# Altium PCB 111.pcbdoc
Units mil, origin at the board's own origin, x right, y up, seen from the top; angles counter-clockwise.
Board outline 2175 x 2208.3 mil, 2 copper layers (Top Layer, Bottom Layer); 49 components, 50 nets, 197 pads, 92 vias.
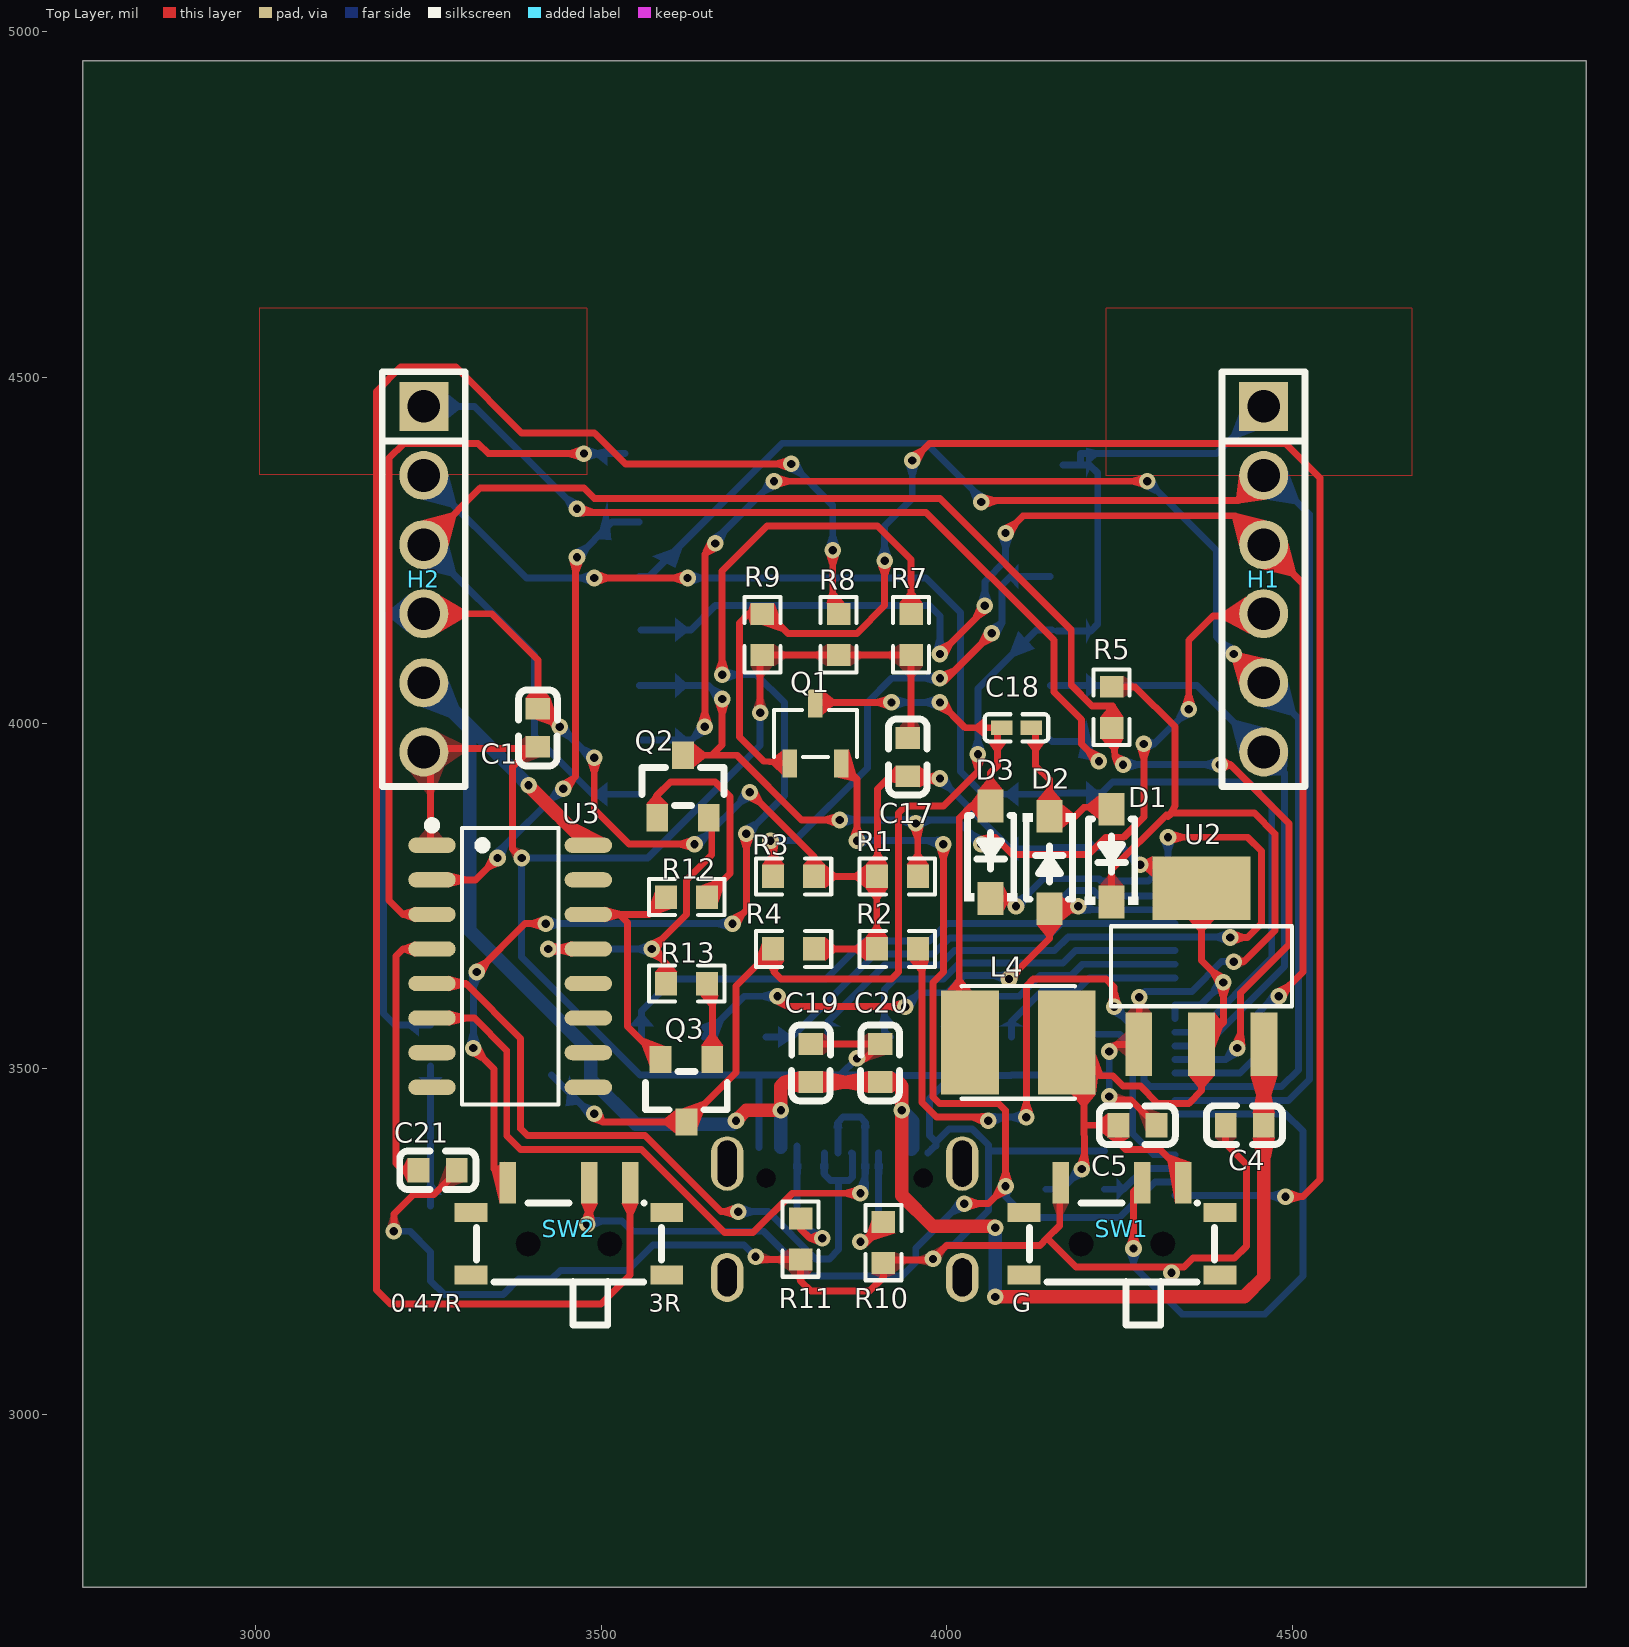
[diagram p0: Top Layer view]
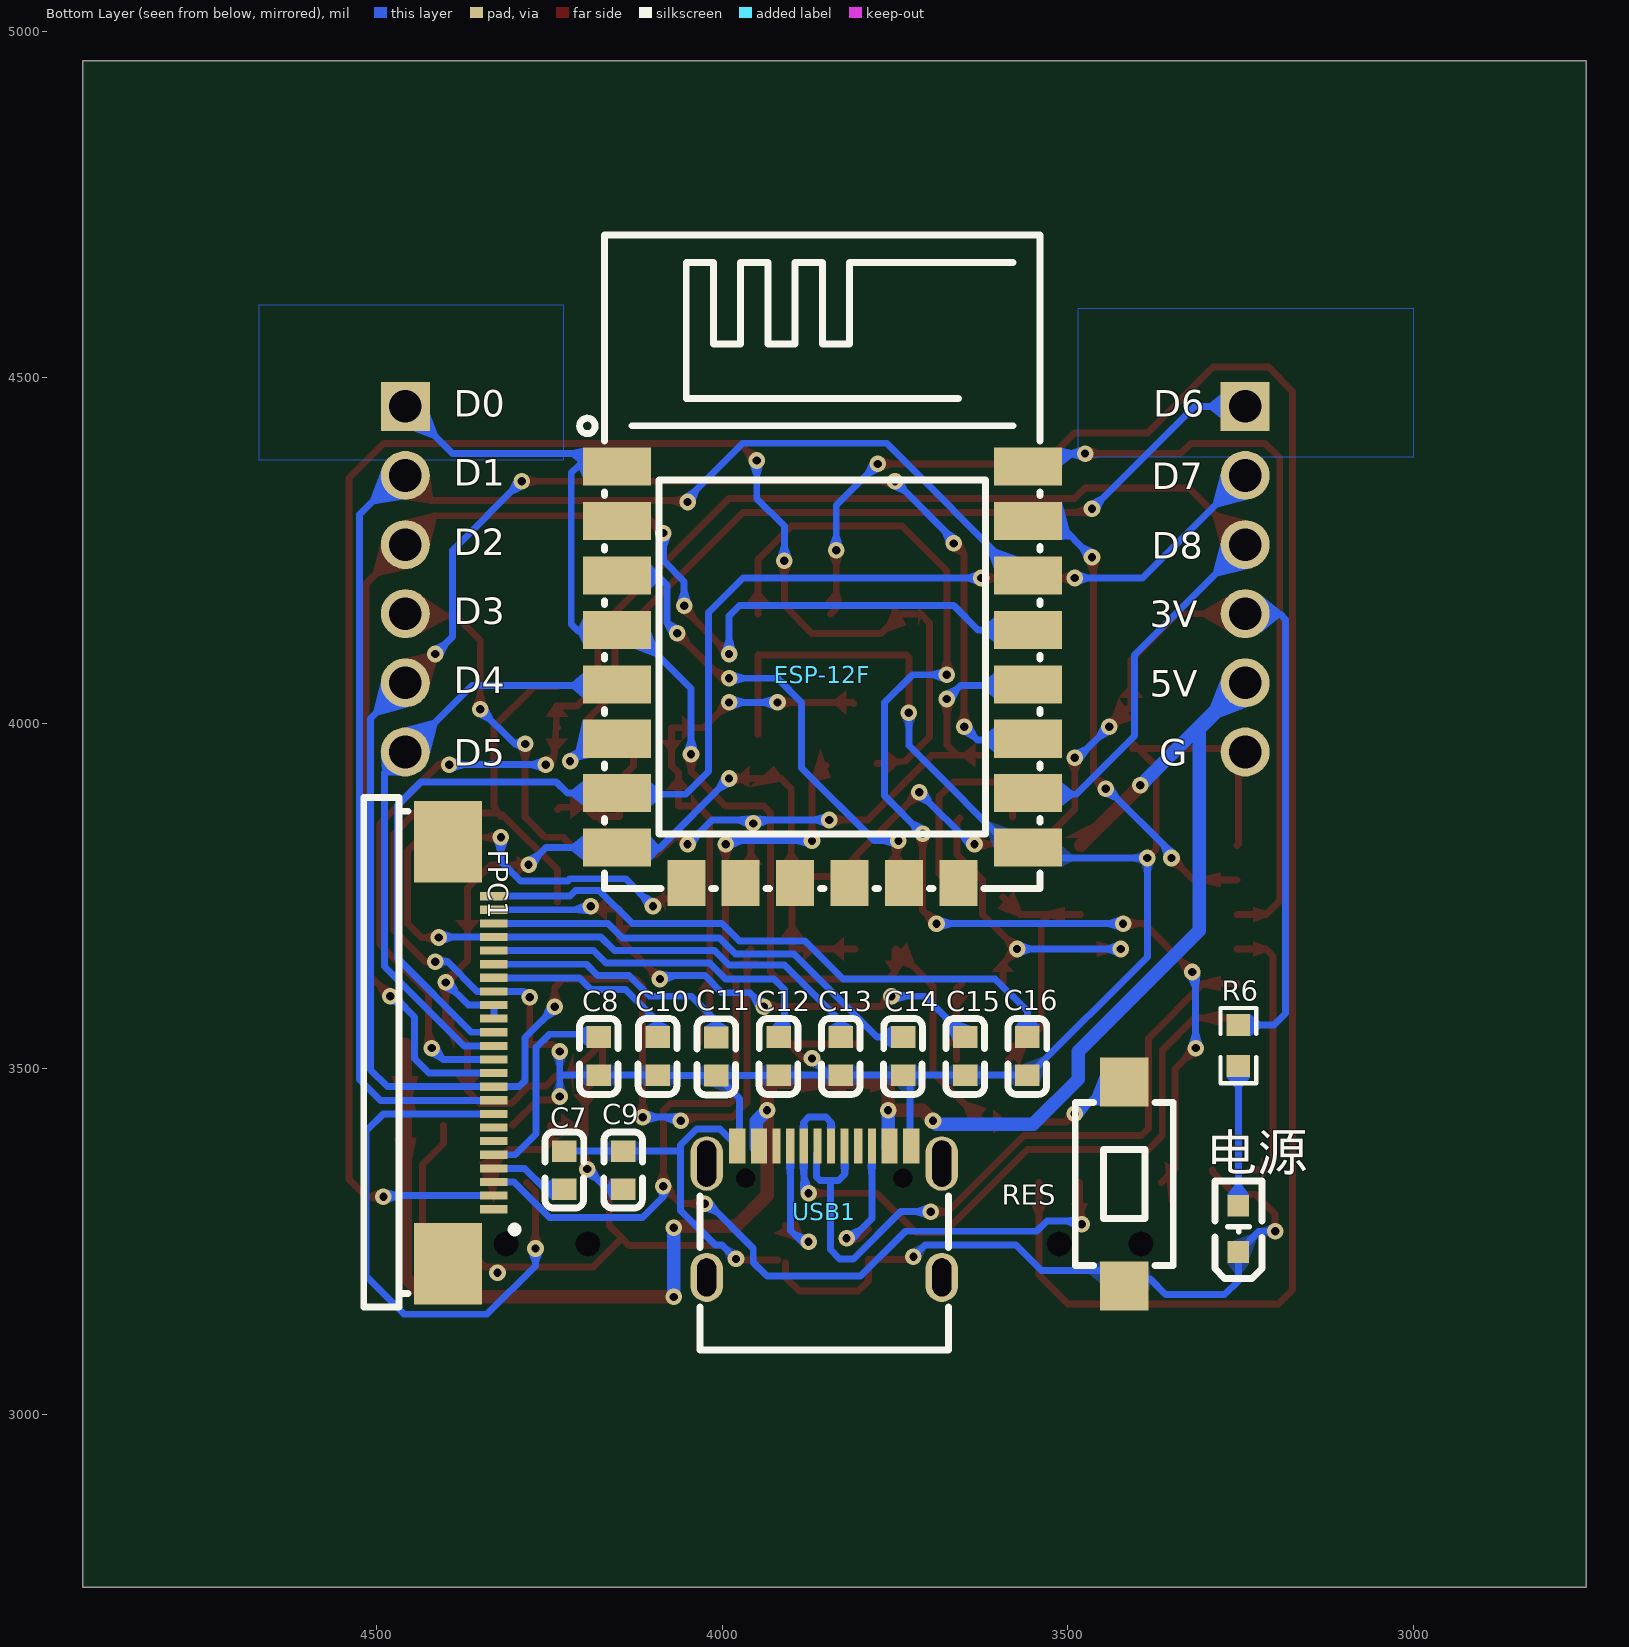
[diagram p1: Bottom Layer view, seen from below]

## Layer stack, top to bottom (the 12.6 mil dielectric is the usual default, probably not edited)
Top Solder: solder mask 0.4, Solder Resist, Dk 3.5
Top Layer: signal copper 1.4
Dielectric 1: dielectric 12.6, FR-4, Dk 4.8
Bottom Layer: signal copper 1.4
Bottom Solder: solder mask 0.4, Solder Resist, Dk 3.5

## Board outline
4925,2750 2750,2750 2750,4958.3 4925,4958.3

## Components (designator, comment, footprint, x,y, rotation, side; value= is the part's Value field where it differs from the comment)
C1 "0.1uF" C0603 3408.56,3993.34 r90 top
C4 "10uF" C0603 4430.9,3418.34 r0 top
C5 "10uF" C0603 4275.78,3418.34 r0 top
C7 "1uF" C0603 4228.34,3353.34 r270 bottom
C8 "1uF" C0603 4178.34,3518.34 r90 bottom
C9 "0.1uF" C0603 4143.34,3353.34 r270 bottom
C10 "1uF" C0603 4093.34,3518.34 r90 bottom
C11 "1uF" C0603 4008.34,3517.73 r90 bottom
C12 "1uF" C0603 3918.34,3518.34 r90 bottom
C13 "1uF" C0603 3828.34,3518.34 r90 bottom
C14 "1uF" C0603 3738.34,3518.34 r90 bottom
C15 "1uF" C0603 3648.34,3518.34 r90 bottom
C16 "1uF" C0603 3558.34,3518.34 r90 bottom
C17 "4.7uF" C0603 3943.34,3950.9 r270 top
C18 "0.1uF" C0402 4100.78,3993.34 r0 top
C19 "0.1uF" C0603 3803.34,3508.34 r270 top
C20 "10uF" C0603 3903.34,3508.34 r270 top
C21 "100nF" C0603 3263.34,3353.34 r180 top
D1 "MBR0530" SOD-123_L2.7-W1.6-LS3.7-RD-1 4238.34,3808.34 r90 top
D2 "MBR0530" SOD-123_L2.7-W1.6-LS3.7-RD-1 4148.34,3798.34 r270 top
D3 "MBR0530" SOD-123_L2.7-W1.6-LS3.7-RD-1 4063.34,3813.34 r90 top
ESP-12F "ESP-12F(ESP8266MOD)" WIFIM-SMD_ESP-12F-ESP8266MOD 3855,4070 r270 bottom
FPC1 "0.5K-BS-24PWB" FPC-SMD_24P-P0.50_HDGC_0.5K-BS-24PWB 4363.34,3523.34 r270 bottom
H1 "Z-211-0611-0021-001" HDR-TH_6P-P2.54-V_Z-211-0611-0021-001 4458.34,4208.34 r270 top
H2 "Z-211-0611-0021-001" HDR-TH_6P-P2.54-V_Z-211-0611-0021-001 3243.34,4208.34 r270 top
L4 "68uH" IND-SMD_L4.0-W4.0_SWPA4018S 4103.34,3538.34 r0 top
Q1 "AO3400" SOT-23-3_L3.0-W1.7-P0.95-LS2.9-BR 3810,3985 r270 top
Q2 "S8050_NPN" SOT-23_L2.9-W1.3-P1.90-LS2.4-BR 3618.34,3908.34 r270 top
Q3 "S8050_NPN" SOT-23_L2.9-W1.3-P1.90-LS2.4-BR 3623.34,3468.34 r90 top
R1 "10kΩ" R0603 3928.34,3778.34 r180 top
R2 "10kΩ" R0603 3928.34,3673.34 r180 top
R3 "10kΩ" R0603 3778.34,3778.34 r0 top
R4 "10kΩ" R0603 3778.34,3673.34 r0 top
R5 "10kΩ" R0603 4238.34,4023 r90 top
R6 "1kΩ" R0603 3253.34,3533.68 r270 bottom
R7 "0.47R" R0603 3948.34,4128 r90 top
R8 "3R" R0603 3843.34,4128 r90 top
R9 "10kΩ" R0603 3733.34,4128 r90 top
R10 "5.1k" R0603 3908.34,3248.68 r90 top
R11 "5.1k" R0603 3788.34,3253.68 r270 top
R12 "10K" R0603 3623.68,3748.34 r0 top
R13 "10K" R0603 3623.68,3623.34 r0 top
RES "TC-3602-4.3-260G" KEY-SMD_L6.0-W3.6-LS8.3-L 3418.34,3333.34 r90 bottom
SW1 "MSK12C02" SW-TH_MSK12C02 4253.34,3268.34 r0 top
SW2 "MSK12C02" SW-TH_MSK12C02 3453.34,3268.34 r0 top
U2 "AMS1117-2.5" SOT-223-3_L6.7-W3.7-P2.30-LS7.0-BR 4368.34,3648.34 r270 top
U3 "CH340C" SOP-16_L10.0-W3.9-P1.27-LS6.0-BL 3368.34,3648.34 r270 top
USB1 "USB_TYPE-C-16P" USB-C-SMD_KH-TYPE-C-16P 3852.32,3293.34 r180 bottom
电源 "19-217/R6C-AL1M2VY/3T" LED0603-R-RD 3253.34,3268.34 r90 bottom

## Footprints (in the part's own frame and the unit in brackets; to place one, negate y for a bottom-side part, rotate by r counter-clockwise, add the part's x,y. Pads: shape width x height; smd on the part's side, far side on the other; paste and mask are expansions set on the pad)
C0402 [mm]
  rect 0.79x0.54 smd: 1(-0.545,0) 2(0.545,0)
  silkscreen extent -1.17,-0.5 1.17,0.5
C0603 [mm]
  rect 0.8x0.9 smd: 1(-0.7,0) 2(0.7,0)
  silkscreen extent -1.41,-0.71 1.39,0.72
FPC-SMD_24P-P0.50_HDGC_0.5K-BS-24PWB [mil]
  rect 11.8x39.4 smd: 1(226.4,33.1) 2(206.7,33.1) 3(187,33.1) 4(167.3,33.1) 5(147.6,33.1) 6(128,33.1) 7(108.3,33.1) 8(88.6,33.1) 9(68.9,33.1) 10(49.2,33.1) 11(29.5,33.1) 12(9.8,33.1) 13(-9.8,33.1) 14(-29.5,33.1) 15(-49.2,33.1) 16(-68.9,33.1) 17(-88.6,33.1) 18(-108.3,33.1) 19(-127.9,33.1) 20(-147.6,33.1) 21(-167.3,33.1) 22(-187,33.1) 23(-206.7,33.1) 24(-226.4,33.1)
  rect 118.1x98.4 smd: 25(-305.1,-33.1) 26(305.1,-33)
  silkscreen extent -369,-155 368,68
HDR-TH_6P-P2.54-V_Z-211-0611-0021-001 [mm]
  rect 1.8x1.8 hole 1.2: 1(-6.35,0)
  round 1.8 hole 1.2: 2(-3.81,0) 3(-1.27,0) 4(1.27,0) 5(3.81,0) 6(6.35,0)
  silkscreen extent -7.62,-1.52 7.62,1.52
IND-SMD_L4.0-W4.0_SWPA4018S [mil]
  rect 83.6x150.4 smd: 1(70,0) 2(-70,0)
  silkscreen extent -82,-82 82,82
KEY-SMD_L6.0-W3.6-LS8.3-L [mm]
  rect 1.8x1.8 smd: 1(-3.75,0) 2(3.75,0)
  silkscreen extent -3,-1.8 3,1.8
LED0603-R-RD [mm]
  rect 0.8x0.8 smd: 1(0.851,0) 2(-0.851,0)
  silkscreen extent -1.82,-0.86 1.77,0.86
R0603 [mil]
  rect 31.75x34.02 smd: 1(-29.66,0) 2(29.66,0)
  silkscreen extent -55,-26 55,26
SOD-123_L2.7-W1.6-LS3.7-RD-1 [mm]
  rect 1.2x0.95 smd: 1(-1.7,0) 2(1.7,0)
  silkscreen extent -1.81,-0.98 1.35,0.98
SOP-16_L10.0-W3.9-P1.27-LS6.0-BL [mm]
  oval 0.56x1.745 smd: 1(-4.445,-2.872) 2(-3.175,-2.872) 3(-1.905,-2.872) 4(-0.635,-2.872) 5(0.635,-2.872) 6(1.905,-2.872) 7(3.175,-2.872) 8(4.445,-2.872) 9(4.445,2.872) 10(3.175,2.872) 11(1.905,2.872) 12(0.635,2.872) 13(-0.635,2.872) 14(-1.905,2.872) 15(-3.175,2.872) 16(-4.445,2.872)
  silkscreen extent -5.33,-3.02 5.08,1.77
SOT-23-3_L3.0-W1.7-P0.95-LS2.9-BR [mil]
  rect 40.85x20.95 smd: 1(43.36,-37.4) 2(43.36,37.4) 3(-43.36,0)
  silkscreen extent -34,-60 34,60
SOT-23_L2.9-W1.3-P1.90-LS2.4-BR [mm]
  rect 1x0.8 smd: 1(1.15,-0.95) 2(1.15,0.95) 3(-1.15,0)
  silkscreen extent -0.7,-1.5 0.7,1.5
SOT-223-3_L6.7-W3.7-P2.30-LS7.0-BR [mm]
  rect 2.34x0.98 smd: 1(2.87,-2.3) 2(2.87,0) 3(2.87,2.3)
  rect 2.34x3.6 smd: 4(-2.87,0)
  silkscreen extent -1.47,-3.33 1.47,3.33
SW-TH_MSK12C02 [mm]
  rect 0.6x1.524 smd: 1(-2.25,1.7) 2(0.75,1.7) 3(2.25,1.7)
  rect 1.2x0.7 smd: 4(-3.6,-1.7) 4(-3.6,0.6) 4(3.6,-1.7) 4(3.6,0.6)
  Multi-Layer board cut-out: -1.05,-0.55 -1.094,-0.355 -1.219,-0.198 -1.4,-0.111 -1.6,-0.111 -1.78,-0.198 -1.905,-0.355 -1.95,-0.55 -1.95,-0.55 -1.905,-0.745 -1.78,-0.902 -1.6,-0.989 -1.4,-0.989 -1.219,-0.902 -1.094,-0.745 -1.05,-0.55
  Multi-Layer board cut-out: 1.95,-0.55 1.906,-0.355 1.781,-0.198 1.6,-0.111 1.4,-0.111 1.22,-0.198 1.095,-0.355 1.05,-0.55 1.05,-0.55 1.095,-0.745 1.22,-0.902 1.4,-0.989 1.6,-0.989 1.781,-0.902 1.906,-0.745 1.95,-0.55
  silkscreen extent -3.4,-3.53 3.4,0.95
USB-C-SMD_KH-TYPE-C-16P [mm]
  oval 1.2x2 hole 0.7 slot 1.7 at 90 deg: 1(-4.32,1.765) 2(4.32,1.765)
  oval 1.2x1.8 hole 0.7 slot 1.4 at 90 deg: 3(-4.32,-2.415) 4(4.32,-2.415)
  rect 0.3x1.3 smd: A1(-3.35,2.415) A4(-2.55,2.415) A5(-1.25,2.415) A6(-0.25,2.415) A7(0.25,2.415) A8(1.25,2.415) A9(2.55,2.415) A12(3.35,2.415) B1(3.05,2.415) B4(2.25,2.415) B5(1.75,2.415) B6(0.75,2.415) B7(-0.75,2.415) B8(-1.75,2.415) B9(-2.25,2.415) B12(-3.05,2.415)
  Multi-Layer board cut-out: -3.24,1.235 -3.205,1.387 -3.108,1.509 -2.968,1.576 -2.812,1.576 -2.672,1.509 -2.575,1.387 -2.54,1.235 -2.54,1.235 -2.575,1.083 -2.672,0.961 -2.812,0.894 -2.968,0.894 -3.108,0.961 -3.205,1.083 -3.24,1.235
  Multi-Layer board cut-out: 2.54,1.235 2.575,1.387 2.672,1.509 2.812,1.576 2.968,1.576 3.108,1.509 3.205,1.387 3.24,1.235 3.24,1.235 3.205,1.083 3.108,0.961 2.968,0.894 2.812,0.894 2.672,0.961 2.575,1.083 2.54,1.235
  silkscreen extent -4.57,-5.08 4.57,0.57
WIFIM-SMD_ESP-12F-ESP8266MOD [mil]
  rect 55.1x98.4 smd: 1(-301.2,-297.3) 2(-222.5,-297.3) 3(-143.7,-297.3) 4(-65,-297.3) 5(13.8,-297.3) 6(92.5,-297.3) 7(171.2,-297.3) 8(250,-297.3) 9(250,297.2) 10(171.2,297.3) 11(92.5,297.3) 12(13.8,297.3) 13(-65,297.2) 14(-143.7,297.3) 15(-222.5,297.3) 16(-301.2,297.3)
  rect 66.9x55.1 smd: 17(301.2,-196.8) 18(301.1,-118.2) 19(301.2,-39.5) 20(301.2,39.3) 21(301.2,118) 22(301.2,196.7)
  silkscreen extent -636,-351 309,315

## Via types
v1: diameter 24.02, hole 12.01, Top Layer to Bottom Layer, 92 vias

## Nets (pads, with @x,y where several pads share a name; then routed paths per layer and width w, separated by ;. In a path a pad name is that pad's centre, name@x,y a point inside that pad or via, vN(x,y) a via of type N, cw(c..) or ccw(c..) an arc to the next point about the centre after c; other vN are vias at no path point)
1: FPC1.3 Q1.2 SW2.2 | length 1900.6
  Top Layer w10: v1(3480,3275) 3482.87,3277.87 SW2.2 ; Q1.2@3850,3939.04 3870,3919.04 v1(3870,3830) ; v1(3995,3825) 3995,3640 3980,3625 3980,3459.13 3989.13,3450 4075,3450 4085,3440 v1(4085,3330) 4060,3305 v1(4025,3305)
  Bottom Layer w10: v1(3480,3275) 3485,3280 3530,3280 3545,3265 3735,3265 3800,3200 3935,3200 3955,3220 3955,3240 4020,3305 v1(4025,3305) ; v1(3870,3830) 3990,3830 v1(3995,3825) ; v1(4085,3330) 4085,3315 4115,3285 4250,3285 4301.34,3336.34 FPC1.3
2: R8.2 SW2.3 | length 2744.1
  Top Layer w10: SW2.3 3541.92,3201.92 3500,3160 3195,3160 3175,3180 3175,4480 3210,4515 3290,4515 3385,4420 3490,4420 3535,4375 v1(3775,4375) ; v1(3835,4250) 3835,4166.01 R8.2
  Bottom Layer w10: v1(3775,4375) 3835,4315 v1(3835,4250)
3: R7.2 SW2.1 | length 1733.3
  Top Layer w10: v1(3315,3530) 3345,3500 3345,3355.04 SW2.1 ; v1(3320,3640) 3390,3710 v1(3420,3710) ; v1(3675,4070) 3675,4220 3740,4285 3900,4285 3948.34,4236.66 R7.2 ; v1(3690,3710) 3710,3730 v1(3710,3840)
  Bottom Layer w10: v1(3315,3530) 3315,3635 v1(3320,3640) ; v1(3420,3710) v1(3690,3710) ; v1(3675,4070) 3725,4070 3765,4030 3765,3895 v1(3710,3840)
8: FPC1.8 SW1.2 | length 827.4
  Top Layer w10: v1(4270,3240) 4270,3322.4 SW1.2
  Bottom Layer w10: v1(4270,3240) 4270,3215 4340,3145 4460,3145 4515,3200 4515,3410 4490.26,3434.74 FPC1.8
$1N49910: R6.2 电源.1 | length 202.2
  Bottom Layer w10: 电源.1 R6.2
$1N54347: C7.2 | length 114.4
  Bottom Layer w10: C7.2 4255.78,3325.78 4286.04,3356.04 4330.24,3356.04
$1N54363: C8.2 | length 299
  Bottom Layer w10: C8.2 4182.44,3550 4250,3550 4269,3531 4269,3406 4299.26,3375.74 4330.24,3375.74
$1N55661: C10.2 | length 285.6
  Bottom Layer w10: C10.2 4093.34,3568.34 4140,3615 4190,3615 4206.64,3631.64 4330.24,3631.64
$1N55690: C11.2 | length 379.3
  Bottom Layer w10: C11.2 4008.34,3568.34 4045,3605 4105,3605 4135,3635 4180,3635 4196.24,3651.24 4330.24,3651.24
$1N55719: C12.2 | length 516
  Bottom Layer w10: C12.2 3910,3554.25 3910,3615 3925,3630 3995,3630 4018.01,3653.01 4168.01,3653.01 4185.94,3670.94 4330.24,3670.94
$1N55777: C14.2 | length 660
  Bottom Layer w10: C14.2 3775.9,3545.9 3896,3666 3981,3666 4004,3689 4144,3689 4165,3710 4329.9,3710 4330.24,3710.34
$1N55910: C16.2 | length 885.1
  Bottom Layer w10: C16.2 3558.34,3583.34 3605,3630 3825,3630 3880,3685 3975,3685 4000,3710 4130,3710 4178.01,3758.01 4211.99,3758.01 4220,3750 4329.99,3750 4330.24,3749.74
$1N60025: C18.1 D3.2 L4.2 Q1.3 | length 779.8
  Top Layer w10: Q1.3 3811.64,4030 v1(3920,4030) ; v1(3990,4030) 4026.66,3993.34 4073.22,3993.34 4073.22,3938.22 4063.34,3928.34 D3.2 4035.27,3880.27 4018.01,3863.01 4018.01,3583.68 4033.34,3568.34 L4.2
  Bottom Layer w10: v1(3920,4030) v1(3990,4030)
$1N60403: C18.2 D1.2 D2.1 | length 233
  Top Layer w10: C18.2@4128.34,3993.34 4128.34,3938.34 4148.34,3918.34 D2.1 4185.27,3865.27 4198.34,3878.34 4235.27,3878.34 D1.2
$1N77678: R10.2 USB1.A5 | length 188.3
  Top Layer w10: v1(3875,3250) 3885,3250 R10.2@3908.34,3273.34
  Bottom Layer w10: v1(3875,3250) 3885,3250 3901.35,3266.35 3901.35,3378.24 USB1.A5@3901.53,3378.42
$1N79361: R11.1 USB1.B5 | length 190.7
  Top Layer w10: R11.1@3788.34,3268.34 3801.69,3255 v1(3820,3255)
  Bottom Layer w10: USB1.B5 3783.34,3388.35 3783.34,3283.34 3811.69,3255 v1(3820,3255)
$1N89698: Q2.1 R12.2 | length 313.3
  Top Layer w10: Q2.1@3580,3864.01 3580,3895 3600,3915 3665,3915 3686.22,3893.78 3686.22,3782.35 3653.34,3749.48 R12.2
$1N89804: Q3.1 R13.2 | length 112.8
  Top Layer w10: R13.2 3660.75,3615.94 Q3.1
$1N90351: C21.2 U3.4 | length 392.6
  Top Layer w10: C21.2 3213.34,3353.34 3203.34,3363.34 3203.34,3663.34 3213.34,3673.34 U3.4
$1N94225: Q3.2 R12.1 U3.14 | length 357.2
  Top Layer w10: U3.14 3526.66,3723.34 ; Q3.2 3538.34,3561.22 3538.34,3711.66 3526.66,3723.34 ; R12.1 3569.02,3723.34 3526.66,3723.34
$1N94557: Q2.2 R13.1 U3.13 | length 494
  Top Layer w10: v1(3423.34,3673.34) U3.13 ; R13.1 3594.02,3652.66 v1(3573.34,3673.34) 3623.34,3723.34 3623.34,3773.34 3660,3810 3660,3858.81 Q2.2
  Bottom Layer w10: v1(3423.34,3673.34) v1(3573.34,3673.34)
$3N116693: FPC1.4
$3N116770: FPC1.5
$3N117995: FPC1.18
$3N118097: FPC1.19
$3N118201: FPC1.20
$3N118416: FPC1.22
$3N118639: FPC1.24
+3V: C1.2 C5.1 C9.2 C17.2 ESP-12F.8 FPC1.15 FPC1.16 H2.4 L4.1 R1.2 R2.2 R3.2 R4.2 R6.1 SW1.3 U2.2 U2.4 | length 3684.4
  Top Layer w10: H2.4 3341.66,4158.34 3408.56,4091.44 C1.2 3414.1,4020.9 v1(3440,3995) ; v1(3490,3950) 3490,3875 3540,3825 v1(3635,3825) ; v1(3715,3900) 3808,3807 R3.2 R1.2 ; R4.2 R2.2 R1.2 ; v1(3990,3920) 3915,3920 3900,3905 3900,3779.66 R1.2 ; v1(4195,3355) 4200,3360 4198.28,3418.34 ; L4.1@4200,3480 4195,3475 L4.1@4192.38,3475 ; 4253.7,3476.3 4240,3490 4221.69,3490 L4.1 4173.34,3496.66 L4.1@4192.38,3475 ; 4255,3475 4280,3475 4305,3450 4350,3450 4368.34,3468.34 U2.2 4400,3567.01 v1(4400,3625) 4368.34,3656.66 U2.4 4334.68,3795 v1(4280,3795) ; SW1.3 4341.92,3349.76 4308.34,3383.34 4258.34,3383.34 4248.22,3393.46 C5.1 4198.28,3418.34 ; L4.1@4192.38,3475 4191.57,3475 L4.1@4198.28,3468.28 ; L4.1@4192.38,3475 L4.1@4198.28,3468.28 ; 4198.28,3418.34 L4.1@4198.28,3468.28
  Bottom Layer w10: H2.4 3193.34,4158.34 3185,4150 3185,3580 3201.66,3563.34 R6.1 ; v1(3440,3995) 3485,3950 v1(3490,3950) ; v1(3635,3825) 3640,3825 v1(3715,3900) ; v1(3990,3920) 4091.66,3818.34 ESP-12F.8@4149.62,3818.34 ; C9.2 4165.78,3325.78 v1(4195,3355) ; ESP-12F.8 4255,3820 v1(4280,3795) ; FPC1.15 FPC1.16 4367.24,3592.24 v1(4400,3625)
+5V: C4.2 C19.2 C20.2 H2.5 U2.3 U3.16 USB1.A4 USB1.A9 USB1.B4 USB1.B9 | length 2794.4
  Top Layer w19.68: v1(3395,3910) 3395,3909.78 U3.16 ; v1(3695,3425) 3710,3440 v1(3760,3440) 3760,3475 3765.78,3480.78 C19.2 C20.2 3929.22,3480.78 3935,3475 v1(3935,3440) 3935,3316.69 3979.54,3272.15 4067.85,3272.15 v1(4070,3270) ; v1(4070,3170) 4430,3170 4458.46,3198.46 C4.2 4458.46,3534.92 U2.3
  Bottom Layer w19.68: 3370,3935 3246.66,4058.34 H2.5 3310,3991.69 3310,3700 3485,3525 3485,3485 3550,3420 3690,3420 v1(3695,3425) ; 3375,3930 v1(3395,3910) ; USB1.B4@3760,3386.49 v1(3760,3440) ; v1(3935,3440) 3950.65,3424.35 3950.65,3385.73 USB1.A4@3948.34,3383.42 ; v1(4070,3170) v1(4070,3270)
ADC: ESP-12F.2
D+: U3.5 USB1.A6 USB1.B6 | length 1048.3
  Top Layer w10: U3.5 3304.12,3623.34 3383.34,3544.12 3383.34,3413.34 3393.34,3403.34 3563.34,3403.34 3673.34,3293.34 v1(3698.34,3293.34)
  Bottom Layer w10: v1(3698.34,3293.34) 3741.66,3293.34 3810,3225 3830,3225 3843.34,3238.34 3843.34,3338.34 ; USB1.B6@3822.79,3378.42 3822.79,3347.21 3831.66,3338.34 3843.34,3338.34 ; USB1.A6@3862.16,3378.42 3863.34,3377.24 3863.34,3343.34 3858.34,3338.34 3843.34,3338.34
D-: U3.6 USB1.A7 USB1.B7 | length 1039.2
  Top Layer w10: U3.6 3316.66,3573.34 3363.34,3526.66 3363.34,3403.34 3383.34,3383.34 3558.34,3383.34 3678.34,3263.34 3719.9,3263.34 3776.56,3320 v1(3875,3320)
  Bottom Layer w10: USB1.A7@3842.48,3378.42 3842.48,3422.48 3850,3430 3875,3430 3881.85,3423.15 USB1.B7 3881.85,3326.85 v1(3875,3320)
EN: ESP-12F.3 R3.1 | length 703.9
  Top Layer w10: v1(3745,3830) 3748.68,3826.32 R3.1 ; v1(3990,4065) 4000,4065 v1(4065,4130)
  Bottom Layer w10: v1(3745,3830) 3780,3830 3885,3935 3885,4030 3920,4065 v1(3990,4065) ; v1(4065,4130) 4080,4145 4080,4200 4092.04,4212.04 ESP-12F.3@4149.62,4212.04
GDR: FPC1.2 Q1.1 R9.2 | length 2590.5
  Top Layer w10: Q1.1 3775.96,3941.64 3735,3945 3700,3980 3700,4145 3712.66,4157.66 R9.2 3742.34,4157.66 3770,4130 3870,4130 3910,4170 v1(3910,4235) ; v1(3950,4380) 3974.78,4404.78 4490.22,4404.78 4540,4355 4540,3340 4515,3315 v1(4490,3315)
  Bottom Layer w10: v1(3910,4235) 3910,4285 3950,4325 v1(3950,4380) ; FPC1.2 4488.36,3316.64 v1(4490,3315) v1@4495,3315
GND: C1.1 C4.1 C5.2 C7.1 C8.1 C9.1 C10.1 C11.1 C12.1 C13.1 C14.1 C15.1 C16.1 C17.1 C19.1 C20.1 C21.1 D1.1 ESP-12F.9 FPC1.17 H2.6 R5.2 R7.1 R8.1 R9.1 R10.1 R11.2 RES.1 SW1.1 U2.1 U3.1 USB1.A1 USB1.A12 USB1.B1 USB1.B12 电源.2 | length 6385.4
  Top Layer w10: v1(3200,3265) 3200,3290 3228.34,3318.34 3258.34,3318.34 3290.9,3350.9 C21.1 ; H2.6 H2.6@3248.34,3963.34 ; U3.1 3253.34,3825.25 3253.34,3958.34 H2.6@3248.34,3963.34 ; v1(3385,3805) 3371.99,3818.01 3371.99,3936.99 C1.1@3398.34,3963.34 ; C1.1@3406.12,3963.34 C1.1@3398.34,3963.34 ; C1.1@3408.34,3973.34 C1.1@3398.34,3963.34 ; v1(3723.34,3228.34) 3727.66,3224.02 R11.2 3788.34,3193.34 3803.34,3178.34 3888.34,3178.34 3908.34,3198.34 R10.1 ; v1(3730,4015) 3730,4095 R9.1 R8.1 R7.1 C17.1@3948.34,3983.46 ; C19.1 C20.1 3882.44,3515 v1(3870,3515) ; R10.1@3919.02,3223.34 3978.34,3223.34 v1(3980,3225) 3999.7,3244.7 4134.7,3244.7 4145,3255 ; SW1.1 4163.34,3333.85 4163.34,3273.34 4145,3255 ; v1(4235,3460) 4240,3455 4266.69,3455 C5.2 ; v1(4235,3525) 4245.35,3535.35 U2.1 4278.34,3535.9 v1(4278.34,3603.34) ; D1.1 4238.34,3788.34 4317.5,3867.5 4320,3865 4322.5,3867.5 ; R5.2 4272.34,4052.66 4330,3995 4330,3880 4322.5,3867.5 ; C4.1 4403.34,3391.66 4433.34,3361.66 4433.34,3243.34 4416.19,3226.19 4356.19,3226.19 4343.34,3213.34 4186.66,3213.34 4145,3255 ; v1(4415,3655) 4430,3655 4475,3700 4475,3840 4445,3870 4325,3870 4322.5,3867.5 ; H2.6@3248.34,3963.34 C1.1@3398.34,3963.34
  Bottom Layer w10: v1(3200,3265) 3223.19,3265 电源.2 3253.34,3193.34 3273.34,3173.34 3358.34,3173.34 3380.7,3195.7 3428.34,3195.7 3440.98,3208.34 3538.34,3208.34 3575,3245 3706.69,3245 v1(3723.34,3228.34) ; USB1.B1@3728.34,3386.34 C14.1@3728.34,3490.78 ; v1(3730,4015) 3730,3967.63 3567.37,3805 v1(3385,3805) 3385,3661.69 3555.9,3490.78 C16.1 C15.1 C14.1@3728.34,3490.78 ; v1(3870,3515) C13.1@3845.78,3490.78 ; USB1.B12@3972.4,3378.42 USB1.B12@3975.37,3381.4 ; USB1.B12@3977.75,3383.34 USB1.A1@3984.21,3388.64 ; v1(3980,3225) 4000,3245 4010,3245 4060,3295 4060,3380.9 4060.9,3380.9 ; USB1.A1 USB1.A1@3984.21,3388.64 ; C7.1 C9.1 4060.9,3380.9 ; v1(4235,3460) 4235,3490 ; v1(4235,3525) 4235,3490 ; v1(4278.34,3603.34) 4286.94,3611.94 FPC1.17 4354.41,3611.94 4397.46,3655 v1(4415,3655) ; C14.1@3728.34,3490.78 C14.1 C13.1 C13.1@3845.78,3490.78 ; C13.1@3845.78,3490.78 C12.1 3918.95,3490.17 C11.1 ; USB1.A1@3984.21,3388.64 USB1.A1@3984.21,3394.21 ; USB1.A1@3984.21,3394.21 4003.2,3413.2 4036.8,3413.2 4060,3390 4060,3381.81 4060.9,3380.9 ; USB1.A1@3984.21,3394.21 3975,3403.42 3975,3456.83 C11.1 ; C11.1 4092.73,3490.17 C10.1 C8.1 4234.22,3490.78 4235,3490
  other v1: 4325,3205
GPIO0: ESP-12F.12 H1.4 Q2.3 R1.1 | length 1470.4
  Top Layer w10: Q2.3 3660,3953.62 ; v1(3675,4035) 3675,3968.62 3660,3953.62 ; v1(3845,3860) 3790,3860 3696.38,3953.62 3660,3953.62 ; v1(3955,3855) 3958,3852 R1.1 ; v1(4050,3825) 4060,3835 4070,3835 4095,3810 4205,3810 4230,3835 4255.95,3835 4285,3864.05 v1(4285,3970) ; v1(4350,4020) 4350,4120 4385,4155 4455,4155 H1.4
  Bottom Layer w10: ESP-12F.12@3555.02,4054.54 3655.46,4054.54 v1(3675,4035) ; v1(3845,3860) 3950,3860 v1(3955,3855) 3960,3860 4015,3860 v1(4050,3825) ; v1(4285,3970) 4300,3970 v1(4350,4020)
GPIO2: ESP-12F.11 FPC1.10 H1.5 R2.1 | length 3093.3
  Top Layer w10: v1(3650,3995) 3650,4245 v1(3665,4260) ; v1(3750,4350) v1(4290,4350) ; R2.1 3964,3667.35 3964,3451 3985,3430 4055,3430 v1(4060,3425) ; v1(4115,3430) 4115,3620 4125,3630 4230,3630 4242.19,3617.81 v1(4242.19,3590) ; v1(4415,4100) 4456.66,4058.34 H1.5
  Bottom Layer w10: ESP-12F.11@3555.02,3975.84 3630.84,3975.84 v1(3650,3995) ; v1(3665,4260) 3665,4265 v1(3750,4350) ; v1(4060,3425) 4065,3430 v1(4115,3430) ; v1@4235,3590 4240,3590 4285,3545 4285,3482.72 4293.57,3474.14 FPC1.10 4484.14,3474.14 4508.5,3498.5 4508.5,4006.5 4458.34,4056.66 H1.5 ; v1(4290,4350) 4390,4250 4390,4125 v1(4415,4100)
GPIO4: ESP-12F.13 FPC1.11 H1.3 | length 2033.4
  Top Layer w10: v1(3990,4100) 4055,4165 v1(4055,4170) ; v1(4085,4275) 4110,4300 4416.69,4300 H1.3 4515,4201.69 4515,3640 v1(4480,3605)
  Bottom Layer w10: ESP-12F.13 3630,4135 3665,4170 3975,4170 3990,4155 v1(3990,4100) ; v1(4055,4170) 4055,4205 4085,4235 v1(4085,4275) ; FPC1.11 4423.84,3493.84 4445,3515 4445,3575 v1@4470,3600
GPIO5: ESP-12F.14 FPC1.9 H1.2 | length 2151.1
  Top Layer w10: v1(4050,4320) 4051.99,4321.99 4421.99,4321.99 H1.2
  Bottom Layer w10: ESP-12F.14@3555.02,4212.04 3569.55,4212.04 3762.51,4405 3970,4405 4050,4325 v1(4050,4320) ; FPC1.9 4494.44,3454.44 4524.5,3484.5 4524.5,4302.19 4468.34,4358.34 H1.2
GPIO12: ESP-12F.6 H2.1 | length 1336.9
  Top Layer w10: v1(3465,4310) 3470,4305 3970,4305 4155,4120 4155,4045 4195,4005 4195,3970 v1(4220,3945)
  Bottom Layer w10: H2.1 3316.66,4458.34 v1(3465,4310) ; ESP-12F.6@4149.62,3975.84 4152.12,3973.34 4191.66,3973.34 v1(4220,3945)
GPIO13: ESP-12F.7 FPC1.14 H2.2 | length 1967.4
  Top Layer w10: v1(3490,4210) v1(3625,4210)
  Bottom Layer w10: H2.2 3391.69,4210 v1(3490,4210) ; v1(3625,4210) 3970,4210 4020,4160 4020,3930 4052.86,3897.14 ESP-12F.7@4141.35,3897.14 ; ESP-12F.7 4223.8,3898.8 4240,3915 4436.02,3915 4470,3881.02 4470,3660 4362.84,3552.84 FPC1.14
GPIO14: ESP-12F.5 FPC1.13 H1.6 | length 876.8
  Bottom Layer w10: ESP-12F.5@4149.62,4054.54 4362.14,4054.54 H1.6 4488.34,3928.34 4488.34,3648.34 4373.14,3533.14 FPC1.13
GPIO15: ESP-12F.10 FPC1.12 H2.3 R5.1 | length 2534.5
  Top Layer w10: H2.3@3260,4275 3325,4340 3475,4340 3490,4325 3990,4325 4180,4135 4180,4055 4210,4025 4240,4025 R5.1@4240,3995.34 ; R5.1 4240,3995 R5.1@4240,3995.34 ; v1(4255,3940) 4243.01,3951.99 R5.1@4240,3995.34 ; v1(4395,3940) 4410,3940 4495,3855 4495,3680 4425,3610 4425,3535 v1(4420,3530)
  Bottom Layer w10: H2.3 3403.34,4098.34 3403.34,3981.66 3487.86,3897.14 ESP-12F.10@3555.02,3897.14 ; v1(4255,3940) v1(4395,3940) ; FPC1.12 4403.54,3513.54 v1(4420,3530)
GPIO16: ESP-12F.1 ESP-12F.4 H1.1 Q3.3 R4.1 RES.2 | length 2026
  Top Layer w10: v1(3490,3435) 3501.66,3423.34 3623.34,3423.34 Q3.3 3695,3494.73 3695,3619.66 R4.1 3750,3672.03 3750,3640 3760,3630 3920,3630 3930,3640 3930,3870 3940,3880 3995,3880 4045,3930 v1(4045,3955)
  Bottom Layer w10: RES.2@3428.34,3490.98 3484.33,3435 v1(3490,3435) ; v1(4045,3955) 4045,4050 4130,4135 ESP-12F.4 ; ESP-12F.4@4159.62,4133.34 4208.34,4133.34 4218.34,4143.34 4218.34,4361.66 4206.66,4373.34 ESP-12F.1@4193.34,4373.34 ; ESP-12F.1@4168.34,4373.34 ESP-12F.1@4193.34,4373.34 ; H1.1 4390,4390 4193.34,4390 ESP-12F.1@4193.34,4373.34
PREVGH: C13.2 D3.1 FPC1.21 | length 1277.4
  Top Layer w10: D3.1 4088.59,3746.41 v1(4100,3735) ; v1(4320,3835) 4435,3835 4455,3815 4455,3710 4435,3690 v1(4410,3690)
  Bottom Layer w10: C13.2 3828.34,3568.34 3910,3650 3990,3650 4011,3671 4156,3671 4175.64,3690.64 FPC1.21 4409.36,3690.64 v1(4410,3690) ; v1(4100,3735) 4140,3775 4220,3775 4223.01,3771.99 4291.99,3771.99 4320,3800 v1@4320,3830
PREVGL: C15.2 D2.2 FPC1.23 | length 804.1
  Top Layer w10: v1(3755,3605) 3770,3590 v1(3940,3590) ; v1(4090,3630) 4148.34,3688.34 D2.2 4186.41,3731.41 v1(4190,3735)
  Bottom Layer w10: C15.2 3707.44,3605 v1(3755,3605) ; v1(3940,3590) 3960,3610 4000,3610 4025,3635 4085,3635 v1(4090,3630) ; v1(4190,3735) 4194.96,3730.04 FPC1.23
RX: ESP-12F.15 U3.2 | length 703.1
  Top Layer w10: U3.2 3318.34,3773.34 v1(3350,3805) ; v1(3445,3905) 3463.01,3923.01 3463.01,4238.01 v1(3465,4240)
  Bottom Layer w10: v1(3350,3805) 3350,3812.54 3442.46,3905 v1(3445,3905) ; v1(3465,4240) 3515.84,4290.84 ESP-12F.15@3555.02,4290.84
TX: ESP-12F.16 U3.3 | length 1066.4
  Top Layer w10: U3.3 3213.34,3723.34 3193.34,3743.34 3193.34,4383.34 3214.78,4404.78 3321.91,4404.78 3336.69,4390 v1(3475,4390)
  Bottom Layer w10: v1(3475,4390) ESP-12F.16@3534.56,4390
"": 
pads on no net: ESP-12F.17 ESP-12F.18 ESP-12F.19 ESP-12F.20 ESP-12F.21 ESP-12F.22 FPC1.1 FPC1.6 FPC1.7 FPC1.25 FPC1.26 SW1.4 SW2.4 U3.7 U3.8 U3.9 U3.10 U3.11 U3.12 U3.15 USB1.1 USB1.2 USB1.3 USB1.4 USB1.A8 USB1.B8

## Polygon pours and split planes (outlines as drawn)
GND on Bottom Layer (solid): 3000,3000 4675,3000 4675,4405 3000,4405
GND on Top Layer (solid, pour order 1): 3005,3000 4675,3000 4675,4405 3005,4405
GND on Top Layer (solid, pour order 2): 3005,4360 3480,4360 3480,4600 3005,4600
GND on Top Layer (solid, pour order 3): 4230,4358.34 4672.99,4358.34 4672.99,4600 4230,4600
GND on Bottom Layer (solid, pour order 4): 4230,4380 4670,4380 4670,4605 4230,4605
GND on Bottom Layer (solid, pour order 5): 3000,4385 3485,4385 3485,4600 3000,4600

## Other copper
Top Layer:
  region net +5V: 4448.62,3465.59 4442.72,3436.06 4474.21,3436.06 4468.31,3465.59
  region net +5V: 4448.62,3371.1 4468.31,3371.1 4474.21,3400.63 4442.72,3400.63
  region net +3V: 4373.34,3474.29 4385.84,3489.29 4350.84,3489.29 4363.34,3474.29
  region net +3V: 4398.24,3558.18 4396.46,3570.55 4387.63,3581.42 4387.63,3529.9
  region net +5V: 4448.62,3459.76 4468.31,3459.76 4478.18,3489.29 4439.6,3489.29
  region net +3V: 4373.34,3700.27 4385.84,3715.27 4350.84,3715.27 4363.34,3700.27
  region net +3V: 4282.48,3800 4282.48,3790 4297.48,3777.5 4297.48,3807.4
  region net +3V: 4217.48,3423.34 4217.48,3413.34 4232.48,3400.84 4232.48,3435.84
  region net +3V: 4243.22,3393.46 4253.22,3393.46 4263.97,3400.63 4232.48,3400.63
  region net +3V: 3433.38,3994.55 3436.88,4005.19 3426.27,4036.65 3405.1,4005.16
  region net +3V: 3403.56,4051.65 3391.06,4036.65 3426.06,4036.65 3413.56,4051.65
  region net +3V: 3905,3810.35 3895,3810.35 3882.81,3795.35 3914.56,3795.35
  region net +3V: 3893.68,3746.34 3903.68,3746.34 3914.56,3761.34 3882.81,3761.34
  region net +3V: 3867.81,3773.34 3882.81,3761.34 3882.81,3795.35 3867.81,3783.34
  region net GPIO0: 3963,3810.35 3953,3810.35 3942.13,3795.35 3973.88,3795.35
  region net +3V: 3867.81,3678.34 3867.81,3668.34 3882.81,3656.34 3882.81,3690.35
  region net +3V: 3893.68,3705.35 3882.81,3690.35 3914.56,3690.35 3903.68,3705.35
  region net GPIO2: 3959,3641.34 3969,3641.34 3973.88,3656.34 3946.5,3656.34
  region net +3V: 3838.88,3773.34 3838.88,3783.34 3823.88,3795.35 3823.88,3761.34
  region net +3V: 3813,3807 3803,3807 3792.13,3795.35 3823.88,3795.35
  region net EN: 3753.68,3810.35 3743.68,3810.35 3732.81,3795.35 3764.56,3795.35
  region net +3V: 3838.88,3678.34 3823.88,3690.35 3823.88,3656.34 3838.88,3668.34
  region net GPIO16: 3728.14,3645.73 3756.42,3656.34 3732.81,3682.22 3722.2,3653.93
  region net GPIO16: 3755,3641.34 3764.56,3656.34 3732.81,3656.34 3745,3641.34
  region net GPIO15: 4247.29,3962.5 4255.35,3977.47 4223.7,3977.47 4237.27,3962.5
  region net GPIO15: 4235,4024.22 4222.5,4009.22 4255.35,4009.22 4245,4024.22
  region net +3V: 4319.51,3365.11 4330.11,3305.27 4351.16,3365.27 4322.88,3375.88
  region net +3V: 3976.06,3915 3976.06,3925 3961.06,3937.5 3961.06,3907.6
  region net +3V: 3915,3915 3961.06,3907.6 3925.63,3937.5 3915,3925
  region net $1N60403: 4123.34,3960.63 4133.34,3960.63 4144.09,3975.63 4112.6,3975.63
  region net $1N60025: 4042.48,3998.34 4042.48,3988.34 4057.48,3975.84 4057.48,4010.84
  region net $1N60025: 4078.22,3960.63 4088.97,3975.63 4057.48,3975.63 4068.22,3960.63
  region net $1N60403: 4204.64,3883.34 4204.64,3873.34 4219.64,3860.84 4219.64,3895.84
  region net PREVGL: 4143.34,3692.79 4153.34,3692.79 4165.84,3707.79 4130.84,3707.79
  region net PREVGL: 4182.04,3726.41 4182.04,3736.41 4167.04,3748.91 4167.04,3713.91
  region net $1N60403: 4182.04,3870.27 4167.04,3882.77 4167.04,3847.77 4182.04,3860.27
  region net $1N60403: 4143.34,3903.9 4130.84,3888.9 4165.84,3888.9 4153.34,3903.9
  region net $1N60025: 4035.27,3885.27 4035.27,3875.27 4044.64,3862.77 4044.64,3897.77
  region net $1N60025: 4068.34,3918.9 4058.34,3918.9 4045.84,3903.9 4080.84,3903.9
  region net PREVGH: 4088.59,3751.41 4082.04,3763.91 4082.04,3728.91 4088.59,3741.41
  region net GDR: 3747.18,3938.98 3762.13,3925.22 3762.13,3960.33 3747.18,3949.02
  region net 1: 3866.46,3915.5 3868.48,3927.63 3857.87,3962.06 3843.07,3921.22
  region net $1N60025: 3835.47,4025 3835.47,4035 3820.47,4047.5 3820.47,4012.5
  region net 3: 3953.34,4188.54 3943.34,4188.54 3931.34,4173.54 3965.35,4173.54
  region net 2: 3840,4188.54 3830,4188.54 3826.34,4173.54 3852.5,4173.54
  region net GDR: 3760.96,4146.11 3750.35,4173.54 3733.46,4141.79 3760.96,4131.97
  region net GDR: 3712.66,4152.66 3716.34,4141.79 3716.34,4173.54 3712.66,4162.66
  region net 2: 3536.92,3290.27 3546.92,3290.27 3553.73,3305.27 3530.11,3305.27
  region net 1: 3477.87,3290.27 3487.87,3290.27 3494.68,3305.27 3471.06,3305.27
  region net 3: 3342.35,3350.62 3352.95,3305.27 3359.51,3365.27 3348.54,3358.57
  region net +5V: 3765.78,3490.63 3765.78,3470.94 3785.63,3465.04 3785.63,3496.53
  region net +5V: 3850.59,3470.94 3850.59,3490.63 3821.06,3496.53 3821.06,3465.04
  region net +5V: 3929.22,3470.94 3929.22,3490.63 3921.06,3496.53 3921.06,3465.04
  region net +5V: 3856.1,3470.94 3885.63,3465.04 3885.63,3496.53 3856.1,3490.63
  region net GPIO5: 4422.98,4360.56 4418.46,4325.53 4425.53,4318.46 4460.56,4322.98
  region net GPIO4: 4460.56,4293.71 4420.22,4303.54 4413.15,4296.46 4422.98,4256.12
  region net GPIO4: 4456.12,4222.98 4497.4,4212.21 4504.47,4219.29 4493.71,4260.56
  region net GPIO0: 4432.5,4182.59 4397.68,4160 4398.63,4150 4437.52,4129.68
  region net GPIO2: 4459.37,4093.76 4418.54,4103.54 4411.49,4096.43 4423.07,4054.94
  region net GPIO15: 3278.71,4256.12 3289.47,4297.4 3282.4,4304.47 3241.12,4293.71
  region net +3V: 3266.78,4131.77 3303.58,4153.34 3303.58,4163.34 3266.78,4184.92
  region net $1N77678: 3881.46,3253.54 3893.93,3251.86 3925.35,3262.47 3891.34,3281.08
  region net RX: 3303.4,3768.34 3303.4,3778.34 3278.58,3784.37 3278.58,3762.32
  region net TX: 3213.34,3718.34 3231.93,3712.32 3231.93,3734.37 3213.34,3728.34
  region net $1N90351: 3213.34,3668.34 3231.93,3662.32 3231.93,3684.37 3213.34,3678.34
  region net D+: 3303.4,3628.34 3278.58,3634.37 3278.58,3612.32 3303.4,3618.34
  region net D-: 3303.4,3578.34 3278.58,3584.37 3278.58,3562.32 3303.4,3568.34
  region net +5V: 3463.45,3855.25 3435.72,3855.14 3458.11,3834.37 3504.76,3834.37
  region net $1N94225: 3526.66,3728.34 3504.76,3734.37 3504.76,3712.32 3526.66,3718.34
  region net $1N94557: 3433.28,3678.34 3433.28,3668.34 3458.11,3662.32 3458.11,3684.37
  region net GPIO0: 3649.09,3948.62 3649.09,3958.62 3634.09,3971.12 3634.09,3936.12
  region net $1N89698: 3575,3895 3565.19,3882.75 3596.69,3882.75 3585,3895
  region net $1N94225: 3559.59,3532.9 3570.19,3504.62 3591.01,3533.3 3562.72,3543.91
  region net GPIO16: 3592.59,3428.34 3592.59,3418.34 3607.59,3405.84 3607.59,3440.84
  region net GPIO16: 3649.7,3442.35 3646.56,3453.36 3618.28,3442.75 3639.09,3414.07
  region net $1N89804: 3665.75,3548.3 3655.75,3548.3 3645,3533.3 3676.49,3533.3
  region net $1N89698: 3672.75,3775.96 3644.47,3765.35 3669.22,3740.6 3679.83,3768.89
  region net $1N94225: 3573.48,3720.73 3601.76,3731.34 3578.15,3757.22 3567.54,3728.93
  region net $1N89804: 3665.75,3591.34 3669.22,3606.34 3643.25,3606.34 3655.75,3591.34
  region net $1N94557: 3599.02,3652.66 3589.02,3652.66 3578.15,3640.35 3609.9,3640.35
  region net $1N90351: 3213.34,3348.34 3220.04,3335.84 3220.04,3370.84 3213.34,3358.34
  region net +3V: 4193.28,3448.14 4203.28,3448.14 4215.14,3463.14 4180.78,3463.14
  region net +3V: 4225.22,3493.54 4215.14,3521.29 4215.14,3463.14 4218.15,3486.46
  region net $1N60025: 4013.01,3628.54 4000.51,3613.54 4035.51,3613.54 4023.01,3628.54
  region net EN: 4053.02,4130.75 4047.03,4119.1 4054.1,4112.03 4065.75,4118.02
  region net EN: 3999.24,4057.34 4010.18,4068.1 4008.26,4080.33 3996.45,4075.13
  region net EN: 3738.86,3819.68 3743.68,3808.13 3753.68,3811.35 3756.01,3825.2
  region net GPIO15: 4255.75,3951.98 4246.54,3955.53 4239.47,3948.46 4243.02,3939.25
  region net GPIO15: 4402.94,3930.99 4410,3935 4410,3945 4402.94,3949.01
  region net GPIO15: 4431.5,3533.47 4430,3547.87 4420,3552.45 4415.12,3540.97
  region net 1: 4094.01,3337.94 4090,3350.41 4080,3350.41 4075.99,3337.94
  region net 1: 4073.02,3330.75 4067.03,3319.1 4074.1,3312.03 4085.75,3318.02
  region net 1: 4032.94,3295.99 4045.41,3300 4045.41,3310 4032.94,3314.01
  region net 1: 3490.64,3280.56 3487.87,3294.08 3477.87,3296.55 3473.16,3284.87
  region net PREVGL: 4179.73,3741.22 4168.17,3736.41 4171.3,3726.41 4185.11,3724.03
  region net +3V: 4206.44,3358.66 4204.62,3373.07 4194.48,3377.52 4189.94,3365.89
  region net +3V: 3714.25,3888.02 3725.9,3882.03 3732.97,3889.1 3726.98,3900.75
  region net +3V: 3627.06,3834.01 3614.59,3830 3614.59,3820 3627.06,3815.99
  region net +3V: 3480.99,3942.06 3485,3929.59 3495,3929.59 3499.01,3942.06
  region net +3V: 3440.75,4006.98 3429.1,4012.97 3422.03,4005.9 3428.02,3994.25
  region net GPIO0: 3665.99,4027.06 3670,4014.59 3680,4014.59 3684.01,4027.06
  region net GPIO2: 3659.01,4002.94 3655,4015.41 3645,4015.41 3640.99,4002.94
  region net GPIO2: 3653.02,4260.75 3647.03,4249.1 3654.1,4242.03 3665.75,4248.02
  region net GPIO2: 3757.94,4340.99 3770.41,4345 3770.41,4355 3757.94,4359.01
  region net GPIO2: 4282.06,4359.01 4269.59,4355 4269.59,4345 4282.06,4340.99
  region net GPIO2: 4414.25,4088.02 4425.9,4082.03 4432.97,4089.1 4426.98,4100.75
  region net PREVGL: 4101.98,3629.25 4107.97,3640.9 4100.9,3647.97 4089.25,3641.98
  region net PREVGL: 3932.06,3599.01 3919.59,3595 3919.59,3585 3932.06,3580.99
  region net PREVGL: 3754.25,3593.02 3765.9,3587.03 3772.97,3594.1 3766.98,3605.75
  region net +3V: 3982.06,3929.01 3969.59,3925 3969.59,3915 3982.06,3910.99
  region net GPIO4: 4001.98,4099.25 4007.97,4110.9 4000.9,4117.97 3989.25,4111.98
  region net GPIO4: 4043.33,4167.19 4038.54,4155.61 4047.79,4150.72 4059.25,4158.77
  region net GPIO4: 4096.98,4274.25 4102.97,4285.9 4095.9,4292.97 4084.25,4286.98
  region net GPIO13: 3617.06,4219.01 3604.59,4215 3604.59,4205 3617.06,4200.99
  region net GPIO13: 3497.94,4200.99 3510.41,4205 3510.41,4215 3497.94,4219.01
  region net D+: 3690.4,3302.35 3677.93,3298.34 3677.93,3288.34 3690.4,3284.34
  region net D-: 3867.06,3329.01 3854.59,3325 3854.59,3315 3867.06,3310.99
  region net $1N94557: 3431.29,3664.34 3443.76,3668.34 3443.76,3678.34 3431.29,3682.35
  region net $1N94557: 3585.33,3672.59 3591.31,3684.24 3584.24,3691.31 3572.59,3685.33
  region net $1N94557: 3572.59,3661.36 3584.24,3655.37 3591.31,3662.44 3585.33,3674.1
  region net GPIO5: 4059.33,4312.44 4071.21,4316.99 4069.52,4326.99 4056.34,4330.2
  region net TX: 3467.06,4399.01 3454.59,4395 3454.59,4385 3467.06,4380.99
  region net RX: 3456.98,3904.25 3462.97,3915.9 3455.9,3922.97 3444.25,3916.98
  region net RX: 3454.8,4233.66 3458.01,4220.48 3468.01,4218.79 3472.56,4230.67
  region net RX: 3338.02,3805.75 3332.03,3794.1 3339.1,3787.03 3350.75,3793.02
  region net GPIO12: 4220.75,3956.98 4209.1,3962.97 4202.03,3955.9 4208.02,3944.25
  region net GPIO12: 3468.47,4298.5 3482.87,4300 3487.45,4310 3475.97,4314.88
  region net $1N60025: 3912.06,4039.01 3899.59,4035 3899.59,4025 3912.06,4020.99
  region net $1N60025: 3989.25,4018.02 4000.9,4012.03 4007.97,4019.1 4001.98,4030.75
  region net GPIO16: 3489.25,3423.02 3498.12,3419.81 3505.19,3426.88 3501.98,3435.75
  region net $1N79361: 3812.06,3264.01 3801.69,3260 3801.69,3250 3812.06,3245.99
  region net $1N77678: 3884.24,3242.34 3895.18,3253.1 3893.26,3265.33 3881.45,3260.13
  region net GPIO0: 3837.06,3869.01 3824.59,3865 3824.59,3855 3837.06,3850.99
  region net GPIO0: 3948.27,3845.06 3953,3833.4 3963,3835.98 3965.71,3849.56
  region net GPIO0: 4061.98,3824.25 4063.54,3831.46 4056.46,3838.54 4049.25,3836.98
  region net GPIO0: 4275.99,3962.06 4280,3949.59 4290,3949.59 4294.01,3962.06
  region net GPIO0: 4359.01,4027.94 4355,4040.41 4345,4040.41 4340.99,4027.94
  region net 3: 3314.25,3518.02 3325.9,3512.03 3332.97,3519.1 3326.98,3530.75
  region net GPIO16: 4035.99,3947.06 4040,3934.59 4050,3934.59 4054.01,3947.06
  region net 3: 3331.98,3639.25 3337.97,3650.9 3330.9,3657.97 3319.25,3651.98
  region net 3: 3412.06,3719.01 3399.59,3715 3399.59,3705 3412.06,3700.99
  region net 3: 3701.98,3709.25 3707.97,3720.9 3700.9,3727.97 3689.25,3721.98
  region net 3: 3700.99,3832.06 3705,3819.59 3715,3819.59 3719.01,3832.06
  region net 3: 3684.01,4077.94 3680,4090.41 3670,4090.41 3665.99,4077.94
  region net 1: 3985.99,3817.06 3990,3804.59 4000,3804.59 4004.01,3817.06
  region net 1: 3879.01,3837.94 3875,3850.41 3865,3850.41 3860.99,3837.94
  region net +3V: 4287.94,3785.99 4300.41,3790 4300.41,3800 4287.94,3804.01
  region net +3V: 4390.99,3617.06 4395,3604.59 4405,3604.59 4409.01,3617.06
  region net +3V: 4400.75,3636.98 4389.1,3642.97 4382.03,3635.9 4388.02,3624.25
  region net GPIO4: 4491.98,3604.25 4497.97,3615.9 4490.9,3622.97 4479.25,3616.98
  region net PREVGH: 4100.75,3746.98 4092.12,3749.95 4085.05,3742.88 4088.02,3734.25
  region net PREVGH: 4417.94,3680.99 4430.41,3685 4430.41,3695 4417.94,3699.01
  region net PREVGH: 4327.94,3825.99 4340.41,3830 4340.41,3840 4327.94,3844.01
  region net 8: 4279.01,3247.94 4275,3260.41 4265,3260.41 4260.99,3247.94
  region net GPIO2: 4251.2,3597.94 4247.19,3610.41 4237.19,3610.41 4233.19,3597.94
  region net GPIO2: 4056.53,3436.5 4042.13,3435 4037.55,3425 4049.03,3420.12
  region net GPIO2: 4124.01,3437.94 4120,3450.41 4110,3450.41 4105.99,3437.94
  region net 2: 3825.99,4242.06 3830,4229.59 3840,4229.59 3844.01,4242.06
  region net 2: 3767.06,4384.01 3754.59,4380 3754.59,4370 3767.06,4365.99
  region net GDR: 4497.94,3305.99 4510.41,3310 4510.41,3320 4497.94,3324.01
  region net GDR: 3961.98,4379.25 3967.97,4390.9 3960.9,4397.97 3949.25,4391.98
  region net GDR: 3900.99,4227.06 3905,4214.59 3915,4214.59 3919.01,4227.06
Bottom Layer:
  region net TX: 3493.5,4395 3493.5,4385 3508.5,4372.5 3508.5,4398.75
  region net RX: 3497.89,4279.96 3497.89,4265.82 3514.7,4264.95 3508.5,4320.05
  region net GPIO5: 3616.43,4251.86 3602.29,4251.86 3574.01,4241.25 3606.9,4224.64
  region net GPIO4: 3622,4130 3622,4140 3607,4152.5 3607,4117.5
  region net GPIO0: 3621.9,4049.54 3621.9,4059.54 3606.9,4072.04 3606.9,4037.04
  region net GPIO2: 3621.9,3970.84 3621.9,3980.84 3606.9,3993.34 3606.9,3958.34
  region net GPIO15: 3493.5,3902.14 3493.5,3892.14 3508.5,3879.64 3508.5,3914.64
  region net +3V: 4091.66,3823.34 4091.66,3813.34 4103.1,3800.84 4103.1,3835.84
  region net +3V: 4216.5,3815 4216.5,3825 4201.5,3837.5 4201.5,3802.5
  region net GPIO13: 4088.1,3902.14 4088.1,3892.14 4103.1,3879.64 4103.1,3914.64
  region net GPIO13: 4216.5,3903.8 4201.5,3916.3 4201.5,3881.3 4216.5,3893.8
  region net GPIO12: 4212.11,3945.82 4212.11,3959.96 4201.5,4005.05 4190.3,3949.95
  region net GPIO14: 4216.5,4049.54 4216.5,4059.54 4201.5,4072.04 4201.5,4037.04
  region net GPIO16: 4092.49,4104.56 4098.91,4096.84 4127.2,4107.45 4103.1,4132.85
  region net GPIO16: 4208.34,4138.34 4201.5,4150.84 4201.5,4115.84 4208.34,4128.34
  region net EN: 4092.04,4217.04 4092.04,4207.04 4103.1,4194.54 4103.1,4229.54
  region net GPIO16: 4206.66,4378.34 4201.5,4390.84 4201.5,4355.84 4206.66,4368.34
  region net GPIO16: 4216.5,4395 4201.5,4398.75 4201.5,4372.5 4216.5,4385
  region net GPIO16: 3464.38,3447.87 3464.38,3462.01 3453.78,3490.3 3449.03,3445.55
  region net $1N49910: 3258.34,3332.59 3248.34,3332.59 3237.6,3317.59 3269.09,3317.59
  region net $1N49910: 3258.34,3473.15 3270.35,3488.15 3236.34,3488.15 3248.34,3473.15
  region net +3V: 3221.34,3558.34 3236.34,3547.47 3236.34,3579.22 3221.34,3568.34
  region net $1N54347: 4255.78,3320.78 4255.78,3330.78 4246.06,3341.53 4246.06,3310.04
  region net $1N54363: 4211.06,3555 4196.06,3561.65 4196.06,3532.5 4211.06,3545
  region net +3V: 4165.78,3320.78 4165.78,3330.78 4161.06,3341.53 4161.06,3310.04
  region net $1N55661: 4098.34,3568.34 4088.34,3568.34 4075.84,3561.65 4110.84,3561.65
  region net $1N55690: 4013.34,3568.34 4003.34,3568.34 3990.84,3561.04 4025.84,3561.04
  region net $1N55719: 3905,3576.65 3900.63,3561.65 3927.5,3561.65 3915,3576.65
  region net PREVGH: 3833.34,3568.34 3823.34,3568.34 3810.84,3561.65 3845.84,3561.65
  region net $1N55777: 3771.06,3540.9 3771.06,3550.9 3756.06,3561.65 3756.06,3530.16
  region net PREVGL: 3676.67,3567.16 3667.63,3572.26 3639.34,3561.65 3666.06,3538.87
  region net $1N55910: 3563.34,3576.65 3553.34,3576.65 3540.84,3561.65 3575.84,3561.65
  region net GPIO16: 4412.3,4419.37 4419.37,4412.3 4447.66,4422.91 4422.91,4447.66
  region net GPIO5: 4463.23,4323.25 4502.98,4316.64 4508.61,4325.15 4492.55,4367.57
  region net GPIO2: 4454.94,4023.07 4496.43,4011.49 4503.74,4018.33 4493.76,4059.37
  region net GPIO14: 4460.56,3993.71 4419.29,4004.47 4412.21,3997.4 4422.98,3956.12
  region net GPIO14: 4456.12,3922.98 4484.81,3924.81 4491.88,3931.88 4493.71,3960.56
  region net GPIO12: 3293.78,4453.34 3293.78,4463.34 3278.78,4475.84 3278.78,4440.84
  region net GPIO13: 3241.12,4322.98 3282.4,4312.21 3289.47,4319.29 3278.71,4360.56
  region net GPIO15: 3241.12,4222.98 3282.4,4212.21 3289.47,4219.29 3278.71,4260.56
  region net +3V: 3219.91,4184.92 3193.34,4163.34 3193.34,4153.34 3219.91,4131.77
  region net +5V: 3243.47,4022.91 3281.08,4010 3294.08,4024.84 3278.48,4062.9
  region net +5V: 3241.12,4022.98 3278.98,4008.79 3292.9,4022.71 3278.71,4060.56
  region net $1N77678: 3896.35,3347.83 3906.35,3347.83 3907.44,3362.83 3895.62,3362.83
  region net D-: 3876.85,3347.83 3886.85,3347.83 3887.76,3362.83 3875.94,3362.83
  region net D-: 3886.85,3423.15 3876.85,3423.15 3875.94,3414.01 3887.76,3414.01
  region net D-: 3837.48,3422.48 3836.57,3414.01 3848.39,3414.01 3847.48,3422.48
  region net D+: 3827.79,3347.83 3828.7,3362.83 3816.88,3362.83 3817.79,3347.83
  region net $1N79361: 3778.34,3347.83 3788.34,3347.83 3789.33,3362.83 3777.51,3362.83
  region net EN: 4076.98,4129.25 4082.97,4140.9 4075.9,4147.97 4064.25,4141.98
  region net EN: 3982.06,4074.01 3969.59,4070 3969.59,4060 3982.06,4055.99
  region net EN: 3752.94,3820.99 3765.41,3825 3765.41,3835 3752.94,3839.01
  region net GPIO15: 4262.94,3930.99 4275.41,3935 4275.41,3945 4262.94,3949.01
  region net GPIO15: 4387.06,3949.01 4374.59,3945 4374.59,3935 4387.06,3930.99
  region net GPIO15: 4408.02,3530.75 4402.03,3519.1 4409.1,3512.03 4420.75,3518.02
  region net 1: 4075.99,3322.06 4080,3315 4090,3315 4094.01,3322.06
  region net 1: 4013.77,3309.25 4005.72,3297.79 4010.61,3288.54 4022.19,3293.33
  region net 1: 3490.97,3270.12 3502.45,3275 3497.87,3285 3483.47,3286.5
  region net PREVGL: 4193.52,3723.52 4207.9,3725.04 4212.43,3735.04 4200.95,3739.92
  region net +3V: 4183.02,3355.75 4177.03,3344.1 4184.1,3337.03 4195.75,3343.02
  region net +3V: 3703.02,3900.75 3697.03,3889.1 3704.1,3882.03 3715.75,3888.02
  region net +3V: 3646.23,3820.75 3654.28,3832.21 3649.39,3841.46 3637.81,3836.67
  region net +3V: 3487.19,3961.67 3475.61,3966.46 3470.72,3957.21 3478.77,3945.75
  region net +3V: 3439.25,3983.02 3450.9,3977.03 3457.97,3984.1 3451.98,3995.75
  region net GPIO0: 3675.75,4046.98 3664.1,4052.97 3657.03,4045.9 3663.02,4034.25
  region net GPIO2: 3638.02,3995.75 3632.03,3984.1 3639.1,3977.03 3650.75,3983.02
  region net GPIO2: 3676.67,4262.81 3681.46,4274.39 3672.21,4279.28 3660.75,4271.23
  region net GPIO2: 3738.02,4350.75 3732.03,4339.1 3739.1,4332.03 3750.75,4338.02
  region net GPIO2: 4289.25,4338.02 4300.9,4332.03 4307.97,4339.1 4301.98,4350.75
  region net GPIO2: 4415.75,4111.98 4404.1,4117.97 4397.03,4110.9 4403.02,4099.25
  region net PREVGL: 4086.53,3641.5 4072.13,3640 4067.55,3630 4079.03,3625.12
  region net PREVGL: 3951.98,3589.25 3957.97,3600.9 3950.9,3607.97 3939.25,3601.98
  region net PREVGL: 3747.06,3614.01 3734.59,3610 3734.59,3600 3747.06,3595.99
  region net +3V: 3989.25,3908.02 4000.9,3902.03 4007.97,3909.1 4001.98,3920.75
  region net GPIO4: 3999.01,4107.94 3995,4120.41 3985,4120.41 3980.99,4107.94
  region net GPIO4: 4064.01,4177.94 4060,4190.41 4050,4190.41 4045.99,4177.94
  region net GPIO4: 4075.99,4267.06 4080,4254.59 4090,4254.59 4094.01,4267.06
  region net GPIO13: 3632.94,4200.99 3645.41,4205 3645.41,4215 3632.94,4219.01
  region net GPIO13: 3482.06,4219.01 3469.59,4215 3469.59,4205 3482.06,4200.99
  region net D+: 3706.29,3284.34 3718.76,3288.34 3718.76,3298.34 3706.29,3302.35
  region net D-: 3886.93,3321.39 3886.85,3336.62 3876.85,3343.57 3872.13,3331.66
  region net $1N94557: 3431.29,3664.34 3443.76,3668.34 3443.76,3678.34 3431.29,3682.35
  region net $1N94557: 3565.4,3682.35 3552.93,3678.34 3552.93,3668.34 3565.4,3664.34
  region net GPIO5: 4054.25,4331.23 4042.79,4339.28 4033.54,4334.39 4038.33,4322.81
  region net TX: 3482.94,4380.99 3495.41,4385 3495.41,4395 3482.94,4399.01
  region net RX: 3433.26,3907.53 3426.32,3895.93 3432.33,3887.79 3443.95,3893.04
  region net RX: 3476.98,4239.25 3482.97,4250.9 3475.9,4257.97 3464.25,4251.98
  region net RX: 3361.07,3809.65 3365.76,3821.23 3355.19,3824.79 3344.01,3815.41
  region net GPIO12: 4220.75,3956.98 4209.1,3962.97 4202.03,3955.9 4208.02,3944.25
  region net GPIO12: 3465.75,4321.98 3454.1,4327.97 3447.03,4320.9 3453.02,4309.25
  region net $1N60025: 3927.94,4020.99 3940.41,4025 3940.41,4035 3927.94,4039.01
  region net $1N60025: 3982.06,4039.01 3969.59,4035 3969.59,4025 3982.06,4020.99
  region net GPIO16: 3486.71,3446.55 3475.14,3451.26 3470.57,3441.68 3478.96,3430.29
  region net $1N79361: 3814.79,3265.82 3803.17,3270.58 3800.07,3259.54 3809.92,3248.48
  region net $1N77678: 3884.24,3242.34 3895.18,3253.1 3893.26,3265.33 3881.45,3260.13
  region net GPIO0: 3852.94,3850.99 3865.41,3855 3865.41,3865 3852.94,3869.01
  region net GPIO0: 3951.53,3866.5 3937.13,3865 3932.55,3855 3944.03,3850.12
  region net GPIO0: 3965.97,3850.12 3977.45,3855 3972.87,3865 3958.47,3866.5
  region net GPIO0: 4050.75,3836.98 4039.1,3842.97 4032.03,3835.9 4038.02,3824.25
  region net GPIO0: 4292.94,3960.99 4300,3965 4300,3975 4292.94,3979.01
  region net GPIO0: 4338.02,4020.75 4332.03,4009.1 4339.1,4002.03 4350.75,4008.02
  region net 3: 3324.01,3537.94 3320,3550.41 3310,3550.41 3305.99,3537.94
  region net GPIO16: 4054.01,3962.94 4050,3975.41 4040,3975.41 4035.99,3962.94
  region net 3: 3308.5,3636.53 3310,3622.13 3320,3617.55 3324.88,3629.03
  region net 3: 3427.94,3700.99 3440.41,3705 3440.41,3715 3427.94,3719.01
  region net 3: 3682.06,3719.01 3669.59,3715 3669.59,3705 3682.06,3700.99
  region net 3: 3721.98,3839.25 3727.97,3850.9 3720.9,3857.97 3709.25,3851.98
  region net 3: 3682.94,4060.99 3695.41,4065 3695.41,4075 3682.94,4079.01
  region net 1: 3991.53,3836.5 3977.13,3835 3972.55,3825 3984.03,3820.12
  region net 1: 3877.94,3820.99 3890.41,3825 3890.41,3835 3877.94,3839.01
  region net +3V: 4280.75,3806.98 4269.1,3812.97 4262.03,3805.9 4268.02,3794.25
  region net +3V: 4388.02,3625.75 4382.03,3614.1 4389.1,3607.03 4400.75,3613.02
  region net GPIO4: 4468.77,3609.25 4460.72,3597.79 4465.61,3588.54 4477.19,3593.33
  region net GPIO4: 4468.77,3609.25 4460.72,3597.79 4465.61,3588.54 4477.19,3593.33
  region net PREVGH: 4111.98,3734.25 4117.97,3745.9 4110.9,3752.97 4099.25,3746.98
  region net PREVGH: 4402.55,3699.42 4389.86,3695.64 4389.32,3685.64 4401.59,3681.43
  region net PREVGH: 4310.99,3827.06 4315,3814.59 4325,3814.59 4329.01,3827.06
  region net 8: 4260.99,3232.06 4265,3219.59 4275,3219.59 4279.01,3232.06
  region net GPIO2: 4239.9,3578.21 4251.51,3571.41 4259.51,3577.56 4254.18,3589.2
  region net GPIO2: 4070.97,3420.12 4082.45,3425 4077.87,3435 4063.47,3436.5
  region net GPIO2: 4107.06,3439.01 4094.59,3435 4094.59,3425 4107.06,3420.99
  region net 2: 3844.01,4257.94 3840,4270.41 3830,4270.41 3825.99,4257.94
  region net 2: 3774.25,4363.02 3785.9,4357.03 3792.97,4364.1 3786.98,4375.75
  region net GDR: 4483.36,3325.01 4470.31,3321.64 4468.93,3311.64 4480.9,3307.17
  region net GDR: 3940.99,4372.06 3945,4359.59 3955,4359.59 3959.01,4372.06
  region net GDR: 3919.01,4242.94 3915,4255.41 3905,4255.41 3900.99,4242.94

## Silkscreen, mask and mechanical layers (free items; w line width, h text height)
Top Overlay:
  text "0.47R" at 3195.57,3148.74 h25.55
  text "3R" at 3568.94,3148.74 h25.55
  text "G" at 4095,3148.65 h25.74
Bottom Overlay:
  text "D6" at 3376.29,4443.43 h38.33
  text "D0" at 4388.41,4443.11 h38.33
  text "D1" at 4388.41,4343.11 h38.33
  text "D7" at 3378.41,4338.11 h38.33
  text "D2" at 4388.41,4243.11 h38.33
  text "D8" at 3378.41,4238.11 h38.33
  text "D3" at 4388.41,4143.11 h38.33
  text "3V" at 3381.29,4138.43 h38.33
  text "D4" at 4388.41,4043.11 h38.33
  text "5V" at 3381.29,4038.43 h38.33
  text "G" at 3367.88,3938.29 h38.61
  text "D5" at 4388.41,3938.11 h38.33
Mechanical 1:
  lines w10: 3143.34,3125.39 4560.67,3125.39 4560.67,4542.71 3143.34,4542.71 3143.34,3125.39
